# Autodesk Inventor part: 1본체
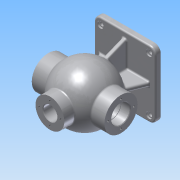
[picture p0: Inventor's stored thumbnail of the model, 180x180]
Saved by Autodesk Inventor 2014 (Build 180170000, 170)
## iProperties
Created: 2017-01
Part Number: 1본체
Material: Aluminum 6061
Document SubType Name: Modeling
Designer: ksu
Density: 2.71 g/cm^3
Appearance: Aluminum - Flat
Mass: 1515.97 g
Surface Area: 1159.86 cm^2
Volume: 559.398 cm^3
Author: ksu
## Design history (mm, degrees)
sketch "Sketch1"
  geometry: L1 (-45.5, -62.5)-(45.5, -62.5); L2 (57.5, -50.5)-(57.5, 50.5); L3 (45.5, 62.5)-(-45.5, 62.5); L4 (-57.5, 50.5)-(-57.5, -50.5); L5 (-57.5, -62.5)-(57.5, 62.5); L6 (57.5, -62.5)-(-57.5, 62.5); A1 r 12 centre (-45.5, 50.5) between (-45.5, 62.5) and (-57.5, 50.5); A2 r 12 centre (45.5, 50.5) between (57.5, 50.5) and (45.5, 62.5); A3 r 12 centre (45.5, -50.5) between (45.5, -62.5) and (57.5, -50.5); A4 r 12 centre (-45.5, -50.5) between (-57.5, -50.5) and (-45.5, -62.5); 1 further point
  constraints: 12 end point, 8 point on circle, 8 point on line, 8 tangent, 4 centre point, 3 equal radius, 2 midpoint, 2 parallel, 1 horizontal, 1 perpendicular
  dimensions: "d0" = 115 distance of L6.end L5.end; "d1" = 125 distance of L5.end L6.start; "d2" = 12 radius of A1
extrude "Extrusion1" new body sketch "Sketch1" distance "d3" = 10; taper "d4" = 0 deg
sketch "Sketch2"
  geometry: A1 r 12 centre (-45.5, 50.5) between (-45.5, 62.5) and (-57.5, 50.5) reference; A2 r 12 centre (-45.5, -50.5) between (-57.5, -50.5) and (-45.5, -62.5) reference; A3 r 12 centre (45.5, -50.5) between (45.5, -62.5) and (57.5, -50.5) reference; A4 r 12 centre (45.5, 50.5) between (57.5, 50.5) and (45.5, 62.5) reference; 5 further points
  constraints: 4 coincident
hole "Hole1" sketch "Sketch2" at (-45.5, 50.5), (-45.5, -50.5), (45.5, -50.5), (45.5, 50.5) diameter "d5" = 8; stored, may be unused: countersink angle "d9" = 90 deg, drill point angle "d11" = 118 deg; dims "d6" = 6, "d7" = 12, "d8" = 3, "d10" = 10
sketch "Sketch3"
  geometry: L1 (62.5, 10)-(62.5, 0) reference; L2 (62.5, 0)-(-62.5, 0) reference; L3 (-62.5, 0)-(-62.5, 10) reference; L4 (-62.5, 10)-(62.5, 10) reference; L5 (0, 138)-(0, 32); A1 r 53 centre (0, 85) between (0, 138) and (0, 32); 1 further point
  constraints: 2 end point, 2 point on circle, 1 centre point, 1 perpendicular
  dimensions: "d13" = 106 diameter of A1
revolve "Revolution1" sketch "Sketch3" stored, may be unused: angle "d14" = 90 deg
workplane "Work Plane1"
sketch "Sketch4"
  geometry: C1 r 27 at (0, 0); 1 further point
  constraints: 1 centre point, 1 coincident
  dimensions: "d16" = 54 diameter of C1
extrude "Extrusion2" join sketch "Sketch4" distance "d17" = 50; taper "d18" = 0 deg
sketch "Sketch5"
  geometry: C1 r 13 at (0, 0); 1 further point
  constraints: 1 centre point, 1 coincident
  dimensions: "d19" = 26 diameter of C1
extrude "Extrusion3" cut sketch "Sketch5" distance "d20" = 50; taper "d21" = 0 deg
sketch "Sketch6"
  geometry: L1 (62.5, 10)-(62.5, 0) reference; L2 (62.5, 0)-(-62.5, 0) reference; L3 (-62.5, 0)-(-62.5, 10) reference; L4 (-62.5, 10)-(62.5, 10) reference; L5 (-27, 130.607)-(-27, 150) reference; L6 (-27, 150)-(-13, 150) reference; L7 (-13, 150)-(-13, 100) reference; L8 (-13, 100)-(13, 100) reference; L9 (13, 100)-(13, 150) reference; L10 (13, 150)-(27, 150) reference; L11 (27, 150)-(27, 130.607) reference; C1 r 31 at (0, 85); A1 r 53 centre (0, 85) between (-27, 130.607) and (0, 32) reference; A2 r 53 centre (0, 85) between (0, 32) and (27, 130.607) reference; 1 further point
  constraints: 1 centre point, 1 coincident
  dimensions: "d22" = 62 diameter of C1
extrude "Extrusion4" join sketch "Sketch6" stored distance "d23" = 136; taper "d24" = 0 deg
sketch "Sketch7"
  geometry: C1 r 31 at (0, 0) reference; C2 r 17.5 at (0, 0); 1 further point
  constraints: 1 centre point, 1 coincident
  dimensions: "d25" = 35 diameter of C2
extrude "Extrusion5" cut sketch "Sketch7" stored distance "d26" = 136; taper "d27" = 0 deg
sketch "Sketch8"
  geometry: C1 r 31 at (0, 0) reference; A1 r 22.5 centre (0, 0) between (22.5, 0) and (0, -22.5); 3 further points
  constraints: 4 point on circle, 1 centre point, 1 coincident
  dimensions: "d28" = 45 diameter of A1
hole "Hole2" sketch "Sketch8" at (22.5, 0), (0, -22.5), (-22.5, 0), (0, 22.5) diameter "d29" = 3.459; stored, may be unused: countersink angle "d33" = 90 deg, drill point angle "d35" = 118 deg; dims "d30" = 12, "d31" = 12, "d32" = 3, "d34" = 15
sketch "Sketch9"
  geometry: C1 r 31 at (0, 0) reference; A1 r 24 centre (0, 0) between (0, 24) and (24, 0); 3 further points
  constraints: 4 point on circle, 1 centre point, 1 coincident
  dimensions: "d36" = 48 diameter of A1
hole "Hole3" sketch "Sketch9" at (0, 24), (24, 0), (0, -24), (-24, 0) diameter "d37" = 3.459; stored, may be unused: countersink angle "d41" = 90 deg, drill point angle "d43" = 118 deg; dims "d38" = 16, "d39" = 12, "d40" = 3, "d42" = 19
sketch "Sketch10"
  geometry: L1 (57.5, 10)-(57.5, 0) reference; L2 (57.5, 0)-(-57.5, 0) reference; L3 (-57.5, 0)-(-57.5, 10) reference; L4 (-57.5, 10)-(57.5, 10) reference; L5 (-42.988, 54)-(-68, 54) reference; L6 (-68, 54)-(-68, 59.27) reference; L7 (-68, 59.27)-(-49, 59.27) reference; L8 (-49, 59.27)-(-47.961, 61) reference; L9 (-47.961, 61)-(-49, 62.73) reference; L10 (-49, 62.73)-(-68, 62.73) reference; L11 (-68, 62.73)-(-68, 67.5) reference; L12 (-68, 67.5)-(68, 67.5) reference; L13 (68, 67.5)-(68, 64.23) reference; L14 (68, 64.23)-(53, 64.23) reference; L15 (53, 64.23)-(51.961, 62.5) reference; L16 (51.961, 62.5)-(53, 60.77) reference; L17 (53, 60.77)-(68, 60.77) reference; L18 (68, 60.77)-(68, 54) reference; L19 (68, 54)-(42.988, 54) reference; L20 (-27, 130.607)-(-27, 150) reference; L21 (-27, 150)-(-13, 150) reference; L22 (-13, 150)-(-13, 116) reference; L23 (-13, 116)-(13, 116) reference; L24 (13, 116)-(13, 150) reference; L25 (13, 150)-(27, 150) reference; L26 (27, 150)-(27, 130.607) reference; L27 (42.988, 116)-(68, 116) reference; L28 (68, 116)-(68, 109.23) reference; L29 (68, 109.23)-(53, 109.23) reference; L30 (53, 109.23)-(51.961, 107.5) reference; L31 (51.961, 107.5)-(53, 105.77) reference; L32 (53, 105.77)-(68, 105.77) reference; L33 (68, 105.77)-(68, 102.5) reference; L34 (68, 102.5)-(-68, 102.5) reference; L35 (-68, 102.5)-(-68, 107.27) reference; L36 (-68, 107.27)-(-49, 107.27) reference; L37 (-49, 107.27)-(-47.961, 109) reference; L38 (-47.961, 109)-(-49, 110.73) reference; L39 (-49, 110.73)-(-68, 110.73) reference; L40 (-68, 110.73)-(-68, 116) reference; L41 (-68, 116)-(-42.988, 116) reference; L42 (47.5, 10)-(27.723, 58.949); L43 (27.723, 58.949)-(0, 58.949); L44 (47.5, 10)-(0, 10); L45 (-27.723, 58.949)-(0, 58.949); L46 (0, 10)-(-47.5, 10); L47 (0, 58.949)-(0, 10); L48 (-47.5, 10)-(-27.723, 58.949); A1 r 53 centre (0, 85) between (-42.988, 54) and (0, 32) reference; A2 r 53 centre (0, 85) between (0, 32) and (42.988, 54) reference; A3 r 53 centre (0, 85) between (42.988, 116) and (27, 130.607) reference; A4 r 53 centre (0, 85) between (-27, 130.607) and (-42.988, 116) reference; 2 further points
  constraints: 14 end point, 2 symmetric about line, 1 collinear, 1 midpoint, 1 perpendicular, 1 point on circle
  dimensions: "d46" = 22 deg angle of L1 L42
extrude "Extrusion6" join sketch "Sketch10" stored distance "d47" = 8; taper "d48" = 0 deg
sketch "Sketch11"
  geometry: L1 (62.5, 10)-(62.5, 0) reference; L2 (62.5, 0)-(-62.5, 0) reference; L3 (-62.5, 0)-(-62.5, 10) reference; L4 (-62.5, 10)-(-4, 10) reference; L5 (-27, 130.607)-(-27, 150) reference; L6 (-27, 150)-(-13, 150) reference; L7 (-13, 150)-(-13, 113.142) reference; L8 (13, 113.142)-(13, 150) reference; L9 (13, 150)-(27, 150) reference; L10 (27, 150)-(27, 130.607) reference; L11 (4, 10)-(62.5, 10) reference; L12 (-52.5, 10)-(-36.349, 49.976); L13 (-36.349, 49.976)-(0, 49.976); L14 (0, 49.976)-(0, 0); L15 (36.349, 49.976)-(0, 49.976); L16 (52.5, 10)-(36.349, 49.976); L17 (-52.5, 10)-(52.5, 10); L18 (-4, 10)-(4, 10) reference; L19 (-4, 10)-(-4, 32.151) reference; L20 (4, 32.151)-(4, 10) reference; C1 r 17.5 at (0, 85) reference; A1 r 53 centre (0, 85) between (-27, 130.607) and (-4, 32.151) reference; A2 r 31 centre (0, 85) between (13, 113.142) and (-13, 113.142) reference; A3 r 53 centre (0, 85) between (4, 32.151) and (27, 130.607) reference; A4 r 53 centre (0, 85) between (-4, 32.151) and (4, 32.151) reference
  constraints: 12 end point, 2 symmetric about line, 1 collinear, 1 parallel, 1 perpendicular, 1 point on line
  dimensions: "d49" = 10 distance from line of L12.start L3; "d50" = 22 deg angle of L3 L12
extrude "Extrusion7" join sketch "Sketch11" stored distance "d51" = 8; taper "d52" = 0 deg
sketch "Sketch12"
  geometry: L1 (-68, 116)-(-42.988, 116) reference; L2 (-68, 54)-(-68, 59.27) reference; L3 (-68, 59.27)-(-49, 59.27) reference; L4 (-49, 59.27)-(-47.961, 61) reference; L5 (-47.961, 61)-(-49, 62.73) reference; L6 (-49, 62.73)-(-68, 62.73) reference; L7 (-68, 62.73)-(-68, 67.5) reference; L8 (-68, 67.5)-(68, 67.5) reference; L9 (68, 67.5)-(68, 64.23) reference; L10 (68, 64.23)-(53, 64.23) reference; L11 (53, 64.23)-(51.961, 62.5) reference; L12 (51.961, 62.5)-(53, 60.77) reference; L13 (53, 60.77)-(68, 60.77) reference; L14 (68, 60.77)-(68, 54) reference; L15 (42.988, 116)-(68, 116) reference; L16 (4, 10)-(57.5, 10) reference; L17 (57.5, 10)-(57.5, 0) reference; L18 (57.5, 0)-(-57.5, 0) reference; L19 (-57.5, 0)-(-57.5, 10) reference; L20 (-57.5, 10)-(-47.5, 10) reference; L21 (-27, 130.607)-(-27, 150) reference; L22 (-27, 150)-(-13, 150) reference; L23 (-13, 150)-(-13, 116) reference; L24 (-13, 116)-(13, 116) reference; L25 (13, 116)-(13, 150) reference; L26 (13, 150)-(27, 150) reference; L27 (27, 150)-(27, 130.607) reference; L28 (68, 54)-(42.988, 54) reference; L29 (68, 116)-(68, 109.23) reference; L30 (68, 109.23)-(53, 109.23) reference; L31 (53, 109.23)-(51.961, 107.5) reference; L32 (51.961, 107.5)-(53, 105.77) reference; L33 (53, 105.77)-(68, 105.77) reference; L34 (68, 105.77)-(68, 102.5) reference; L35 (68, 102.5)-(-68, 102.5) reference; L36 (-68, 102.5)-(-68, 107.27) reference; L37 (-68, 107.27)-(-49, 107.27) reference; L38 (-49, 107.27)-(-47.961, 109) reference; L39 (-47.961, 109)-(-49, 110.73) reference; L40 (-49, 110.73)-(-68, 110.73) reference; L41 (-68, 110.73)-(-68, 116) reference; L42 (-42.988, 54)-(-68, 54) reference; L43 (0, 128)-(0, 42); L44 (-47.5, 10)-(-33.719, 44.109) reference; L45 (4, 32.151)-(4, 10) reference; A1 r 53 centre (0, 85) between (42.988, 116) and (27, 130.607) reference; A2 r 53 centre (0, 85) between (-27, 130.607) and (-42.988, 116) reference; A3 r 53 centre (0, 85) between (4, 32.151) and (42.988, 54) reference; A4 r 53 centre (0, 85) between (-42.988, 54) and (-33.719, 44.109) reference; A5 r 43 centre (0, 85) between (0, 128) and (0, 42); 1 further point
  constraints: 2 end point, 2 point on circle, 1 centre point, 1 coincident, 1 perpendicular
revolve "Revolution2" sketch "Sketch12" stored, may be unused: angle "d54" = 90 deg
sketch "Sketch13"
  geometry: L1 (-68, 116)-(-42.988, 116) reference; L2 (-68, 54)-(-68, 59.27) reference; L3 (-68, 59.27)-(-49, 59.27) reference; L4 (-49, 59.27)-(-47.961, 61) reference; L5 (-47.961, 61)-(-49, 62.73) reference; L6 (-49, 62.73)-(-68, 62.73) reference; L7 (-68, 62.73)-(-68, 67.5) reference; L8 (-68, 67.5)-(-39.278, 67.5) reference; L9 (39.278, 67.5)-(68, 67.5) reference; L10 (68, 67.5)-(68, 64.23) reference; L11 (68, 64.23)-(53, 64.23) reference; L12 (53, 64.23)-(51.961, 62.5) reference; L13 (51.961, 62.5)-(53, 60.77) reference; L14 (53, 60.77)-(68, 60.77) reference; L15 (68, 60.77)-(68, 54) reference; L16 (42.988, 116)-(68, 116) reference; L17 (4, 10)-(57.5, 10) reference; L18 (57.5, 10)-(57.5, 0) reference; L19 (57.5, 0)-(-57.5, 0) reference; L20 (-57.5, 0)-(-57.5, 10) reference; L21 (-57.5, 10)-(-47.5, 10) reference; L22 (27, 150)-(27, 130.607) reference; L23 (68, 54)-(42.988, 54) reference; L24 (68, 116)-(68, 109.23) reference; L25 (68, 109.23)-(53, 109.23) reference; L26 (53, 109.23)-(51.961, 107.5) reference; L27 (51.961, 107.5)-(53, 105.77) reference; L28 (53, 105.77)-(68, 105.77) reference; L29 (68, 105.77)-(68, 102.5) reference; L30 (68, 102.5)-(39.278, 102.5) reference; L31 (13, 125.988)-(13, 150) reference; L32 (13, 150)-(27, 150) reference; L33 (-27, 130.607)-(-27, 150) reference; L34 (-27, 150)-(-13, 150) reference; L35 (-13, 150)-(-13, 125.988) reference; L36 (-39.278, 102.5)-(-68, 102.5) reference; L37 (-68, 102.5)-(-68, 107.27) reference; L38 (-68, 107.27)-(-49, 107.27) reference; L39 (-49, 107.27)-(-47.961, 109) reference; L40 (-47.961, 109)-(-49, 110.73) reference; L41 (-49, 110.73)-(-68, 110.73) reference; L42 (-68, 110.73)-(-68, 116) reference; L43 (-42.988, 54)-(-68, 54) reference; L44 (-68, 102.5)-(-68, 67.5); L45 (-52, 85)-(-50.25, 85); L46 (-52, 85)-(-50.25, 85); L47 (-50.25, 85)-(-50.25, 103.5); L48 (-50.25, 103.5)-(-52, 103.5); L49 (-52, 103.5)-(-52, 85); L50 (-47.5, 10)-(-33.719, 44.109) reference; L51 (4, 32.151)-(4, 10) reference; A1 r 43 centre (0, 85) between (-39.278, 67.5) and (0, 42) reference; A2 r 43 centre (0, 85) between (0, 42) and (39.278, 67.5) reference; A3 r 53 centre (0, 85) between (42.988, 116) and (27, 130.607) reference; A4 r 53 centre (0, 85) between (-27, 130.607) and (-42.988, 116) reference; A5 r 53 centre (0, 85) between (4, 32.151) and (42.988, 54) reference; A6 r 43 centre (0, 85) between (39.278, 102.5) and (13, 125.988) reference; A7 r 43 centre (0, 85) between (-13, 125.988) and (-39.278, 102.5) reference; A8 r 53 centre (0, 85) between (-42.988, 54) and (-33.719, 44.109) reference; 1 further point
  constraints: 12 end point, 2 parallel, 2 perpendicular, 1 horizontal
  dimensions: "d56" = 1.75 distance of L48.end L47.end; "d57" = 18.5 distance of L45.end L47.end
revolve "Revolution3" sketch "Sketch13" stored, may be unused: angle "d58" = 90 deg
sketch "Sketch14"
  geometry: C1 r 27 at (0, 0) reference; A1 r 20 centre (0, 0) between (0, 20) and (-20, 0); 2 further points
  constraints: 4 point on circle, 1 centre point, 1 coincident
  dimensions: "d59" = 40 diameter of A1
hole "Hole4" sketch "Sketch14" at (0, 20), (-20, 0), (20, 0), (0, -20) diameter "d60" = 3.459; stored, may be unused: countersink angle "d64" = 90 deg, drill point angle "d66" = 118 deg; dims "d61" = 9, "d62" = 12, "d63" = 3, "d65" = 11
workplane "Work Plane2"
sketch "Sketch15"
  geometry: L1 (-27, 150)-(27, 150) reference; L2 (-27, 150)-(-27, 130.607) reference; L3 (27, 150)-(27, 130.607) reference; L4 (-27, 130.607)-(27, 130.607) reference; L5 (-20.739, 143.002)-(20.739, 143.002); L6 (20.739, 143.002)-(20.739, 136.998); L7 (20.739, 136.998)-(-20.739, 136.998); L8 (-20.739, 136.998)-(-20.739, 143.002); 1 further point
  constraints: 2 other
emboss "Emboss1" sketch "Sketch15" dims "d0" = 115, "d1" = 125, "d2" = 12, "d70" = 0.5, "d71" = 0
fillet "Fillet1" dims "d72" = 3
chamfer "Chamfer1" distance "d73" = 1; stored, may be unused: second distance "d74" = 2, angle "d75" = 45 deg
fillet "Fillet2" dims "d76" = 3
fillet "Fillet3" dims "d77" = 3
chamfer "Chamfer2" distance "d78" = 1; stored, may be unused: second distance "d79" = 2, angle "d80" = 45 deg
mirror "Mirror1"
fillet "Fillet4" dims "d82" = 3
fillet "Fillet5" dims "d83" = 3
sketch "Sketch16"
  geometry: L1 (-49, 107.27)-(-47.961, 109) reference; L2 (-47.961, 109)-(-49, 110.73) reference; L3 (-49, 110.73)-(-68, 110.73) reference; L4 (-68, 110.73)-(-68, 116) reference; L5 (-68, 116)-(-44.497, 116) reference; L6 (-27, 132.286)-(-27, 150) reference; L7 (-27, 150)-(-21.73, 150) reference; L8 (-21.73, 150)-(-21.73, 139) reference; L9 (-21.73, 139)-(-20, 137.961) reference; L10 (-20, 137.961)-(-18.271, 139) reference; L11 (-18.271, 139)-(-18.271, 150) reference; L12 (-18.271, 150)-(-14, 150) reference; L13 (-14, 150)-(-13, 149) reference; L14 (-13, 149)-(-13, 125.988) reference; L15 (-39.278, 102.5)-(-50.25, 102.5) reference; L16 (-50.25, 102.5)-(-50.25, 103.5) reference; L17 (-50.25, 103.5)-(-52, 103.5) reference; L18 (-52, 103.5)-(-52, 102.5) reference; L19 (-52, 102.5)-(-67, 102.5) reference; L20 (-67, 102.5)-(-68, 103.5) reference; L21 (-68, 103.5)-(-68, 107.27) reference; L22 (-68, 107.27)-(-49, 107.27) reference; L23 (53, 64.23)-(51.961, 62.5) reference; L24 (51.961, 62.5)-(53, 60.77) reference; L25 (53, 60.77)-(68, 60.77) reference; L26 (68, 60.77)-(68, 54) reference; L27 (68, 54)-(44.497, 54) reference; L28 (33.719, 44.109)-(46.742, 11.876) reference; L29 (49.524, 10)-(54.5, 10) reference; L30 (57.5, 7)-(57.5, 0) reference; L31 (57.5, 0)-(-57.5, 0) reference; L32 (-57.5, 0)-(-57.5, 7) reference; L33 (-54.5, 10)-(-47.5, 10) reference; L34 (-47.5, 10)-(-34.526, 42.113) reference; L35 (-44.497, 54)-(-68, 54) reference; L36 (-68, 54)-(-68, 59.27) reference; L37 (-68, 59.27)-(-49, 59.27) reference; L38 (-49, 59.27)-(-47.961, 61) reference; L39 (-47.961, 61)-(-49, 62.73) reference; L40 (-49, 62.73)-(-68, 62.73) reference; L41 (-68, 62.73)-(-68, 66.5) reference; L42 (-68, 66.5)-(-67, 67.5) reference; L43 (-67, 67.5)-(-52, 67.5) reference; L44 (-52, 67.5)-(-52, 66.5) reference; L45 (-52, 66.5)-(-50.25, 66.5) reference; L46 (-50.25, 66.5)-(-50.25, 67.5) reference; L47 (-50.25, 67.5)-(-39.278, 67.5) reference; L48 (0, 42)-(0, 58.949) reference; L49 (0, 58.949)-(27.723, 58.949) reference; L50 (27.723, 58.949)-(29.744, 53.947) reference; L51 (39.278, 67.5)-(67, 67.5) reference; L52 (67, 67.5)-(68, 66.5) reference; L53 (68, 66.5)-(68, 64.23) reference; L54 (68, 64.23)-(53, 64.23) reference; L55 (53, 109.23)-(51.961, 107.5) reference; L56 (51.961, 107.5)-(53, 105.77) reference; L57 (53, 105.77)-(68, 105.77) reference; L58 (68, 105.77)-(68, 103.5) reference; L59 (68, 103.5)-(67, 102.5) reference; L60 (67, 102.5)-(39.278, 102.5) reference; L61 (13, 125.988)-(13, 149) reference; L62 (13, 149)-(14, 150) reference; L63 (14, 150)-(18.271, 150) reference; L64 (18.271, 150)-(18.271, 139) reference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; A1 r 3 centre (-44.497, 119) between (-44.497, 116) and (-42.113, 117.179) reference; A2 r 53 centre (0, 85) between (-28.393, 129.753) and (-42.113, 117.179) reference; A3 r 3 centre (-30, 132.286) between (-28.393, 129.753) and (-27, 132.286) reference; A4 r 43 centre (0, 85) between (-13, 125.988) and (-39.278, 102.5) reference; A5 r 3 centre (44.497, 51) between (44.497, 54) and (42.113, 52.821) reference; A6 r 53 centre (0, 85) between (33.719, 44.109) and (42.113, 52.821) reference; A7 r 3 centre (49.524, 13) between (46.742, 11.876) and (49.524, 10) reference; A8 r 3 centre (54.5, 7) between (57.5, 7) and (54.5, 10) reference; A9 r 3 centre (-54.5, 7) between (-54.5, 10) and (-57.5, 7) reference; A10 r 3 centre (-37.307, 43.237) between (-34.526, 42.113) and (-35.309, 45.474) reference; A11 r 53 centre (0, 85) between (-42.113, 52.821) and (-35.309, 45.474) reference; A12 r 3 centre (-44.497, 51) between (-42.113, 52.821) and (-44.497, 54) reference; A13 r 43 centre (0, 85) between (-39.278, 67.5) and (0, 42) reference; A14 r 43 centre (0, 85) between (29.744, 53.947) and (39.278, 67.5) reference; A15 r 43 centre (0, 85) between (39.278, 102.5) and (13, 125.988) reference; A16 r 3 centre (30, 132.286) between (27, 132.286) and (28.393, 129.753) reference; A17 r 53 centre (0, 85) between (42.113, 117.179) and (28.393, 129.753) reference; A18 r 3 centre (44.497, 119) between (42.113, 117.179) and (44.497, 116) reference; A19 r 43 centre (0, 85) between (0, 42) and (0, 128); 1 further point
  constraints: 4 end point, 2 point on circle, 1 centre point, 1 coincident, 1 perpendicular
revolve "Revolution4" sketch "Sketch16" stored, may be unused: angle "d85" = 90 deg
body "Solid1"
node "Project Cut Edges1"
node "Project Cut Edges2"
node "Project Cut Edges3"
node "Project Cut Edges4"
node "Project Cut Edges5"
node "Project Cut Edges6"
node "Project Cut Edges7"
other parameters: "d53" = 86, "d67" = -27
